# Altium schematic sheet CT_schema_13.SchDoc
size 387 x 385 mm
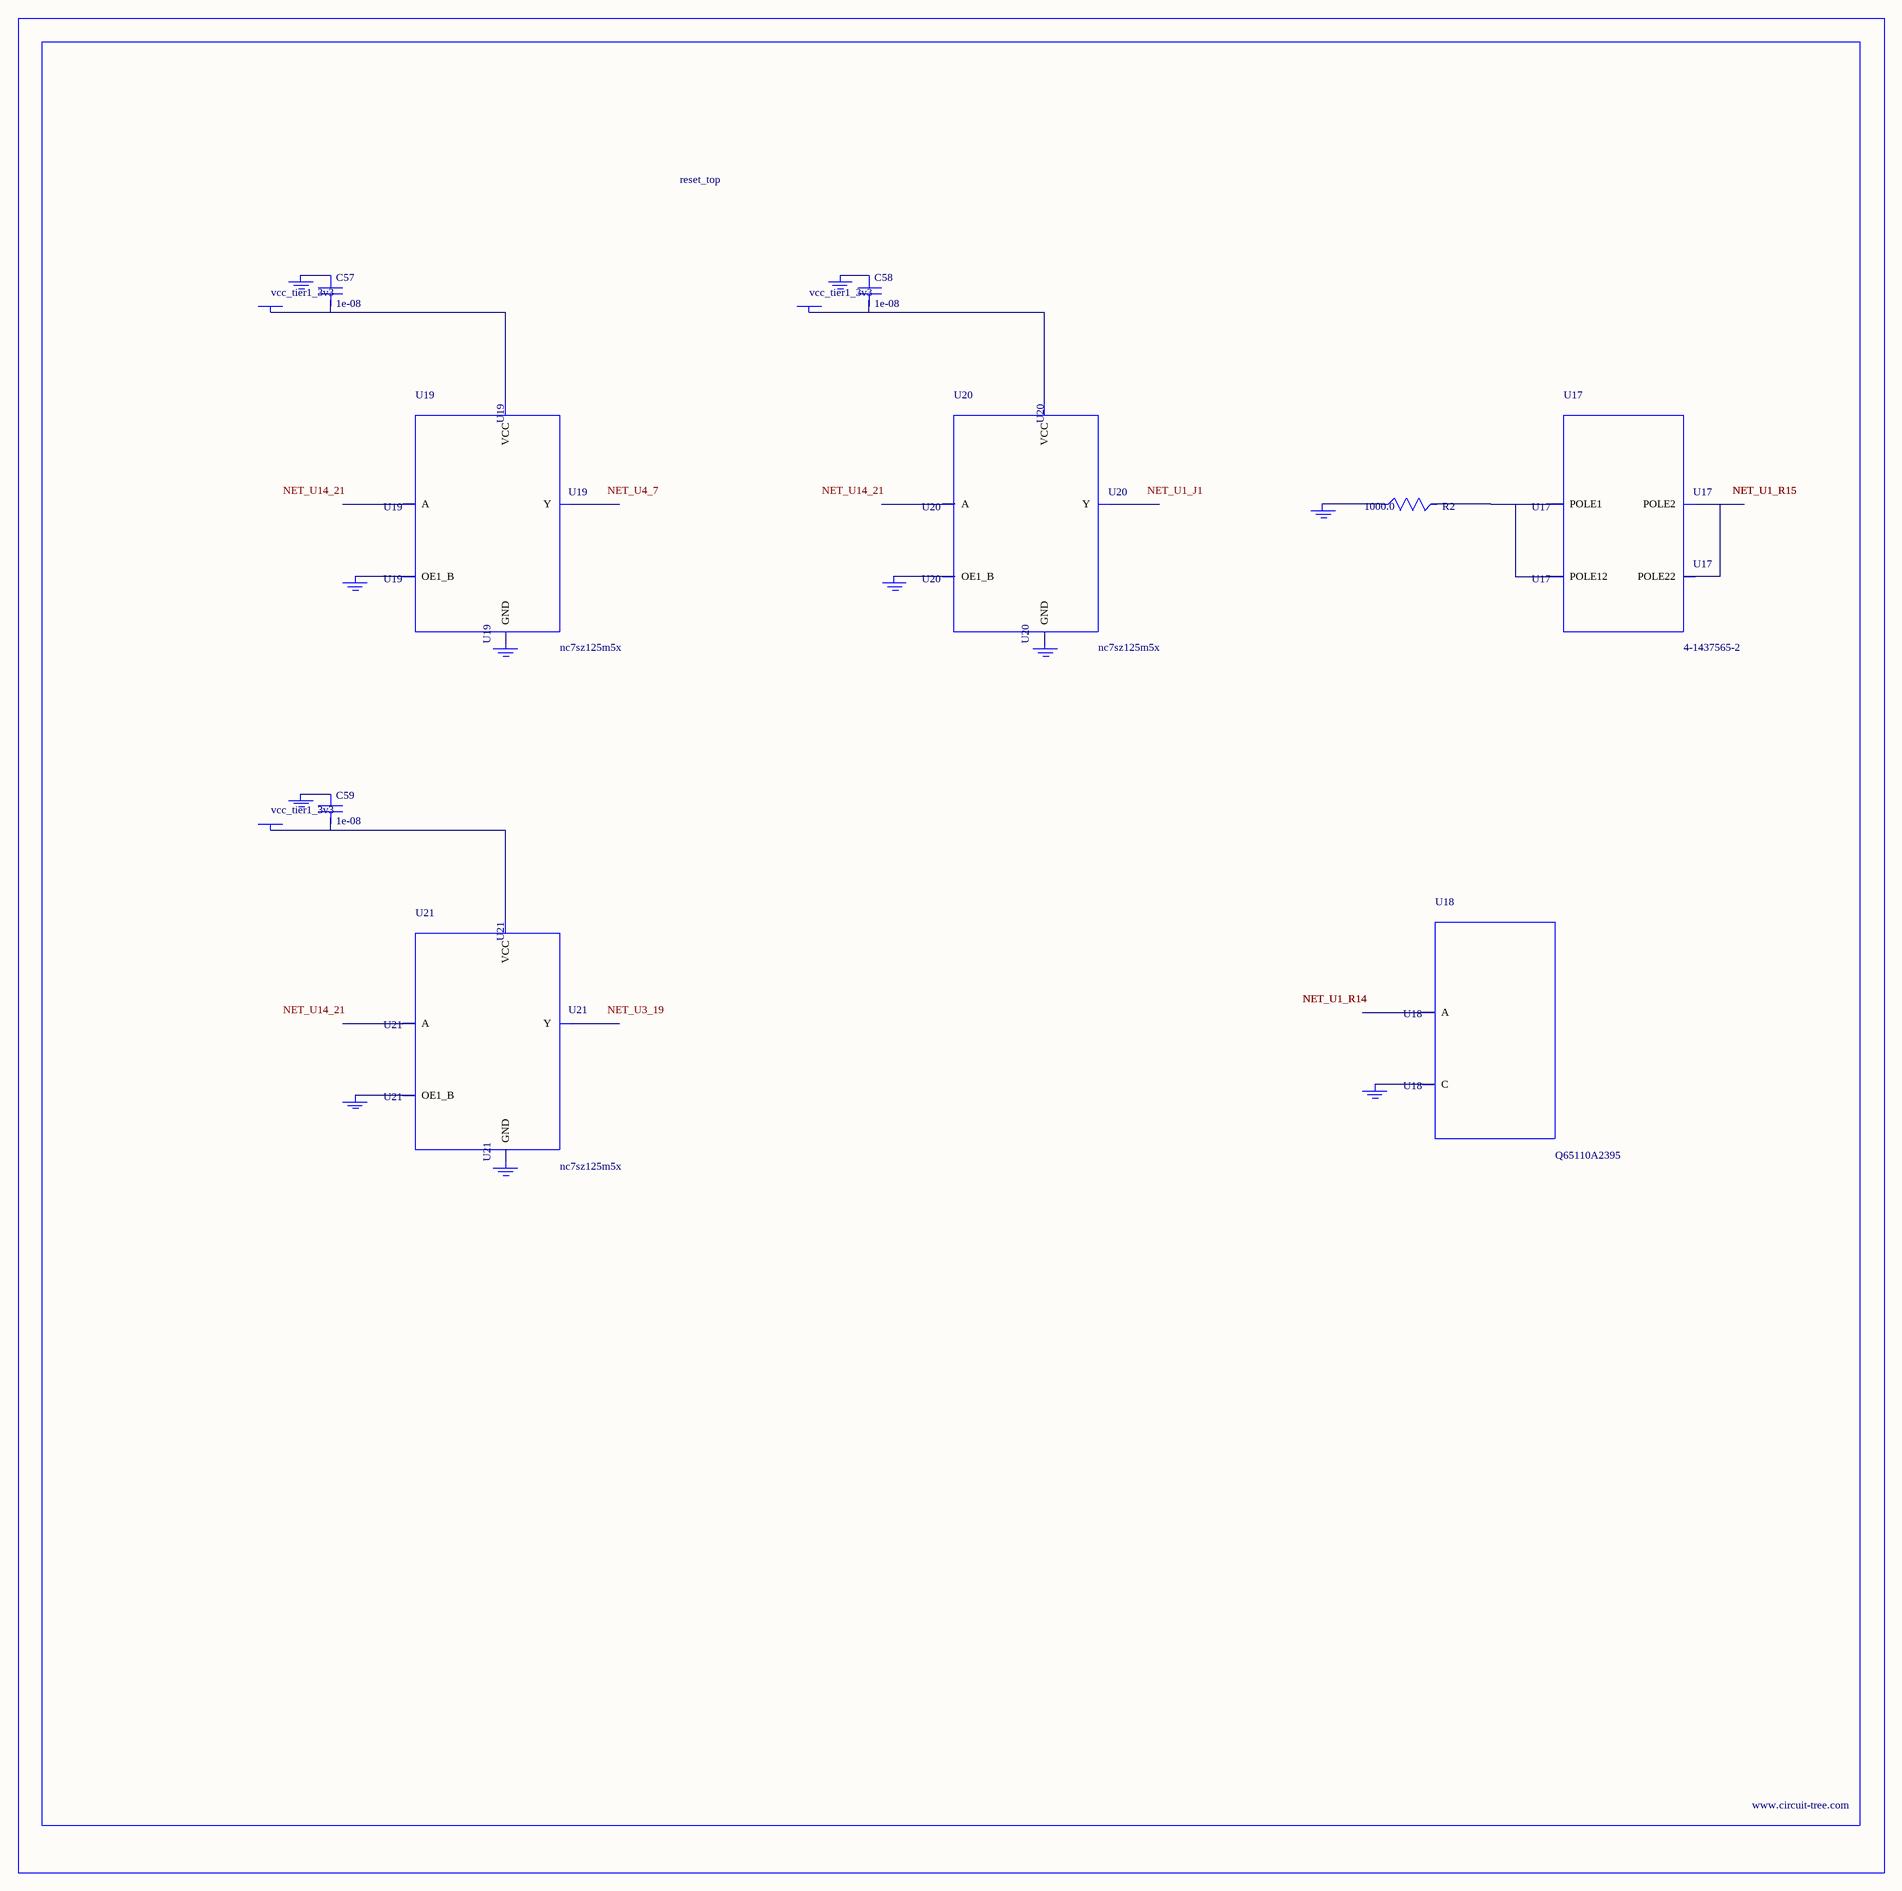
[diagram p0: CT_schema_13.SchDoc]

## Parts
BORDER12  (no value)
C57  1e-08  [C0402]
C58  1e-08  [C0402]
C59  1e-08  [C0402]
GND_INSTANCE_12_0  (no value)
GND_INSTANCE_12_1  (no value)
GND_INSTANCE_12_2  (no value)
GND_INSTANCE_12_3  (no value)
GND_INSTANCE_12_4  (no value)
GND_INSTANCE_12_5  (no value)
GND_INSTANCE_12_6  (no value)
GND_INSTANCE_12_7  (no value)
GND_INSTANCE_12_8  (no value)
GND_INSTANCE_12_9  (no value)
GND_INSTANCE_12_10  (no value)
POWER_INSTANCE_12_0  vcc_tier1_3v3
POWER_INSTANCE_12_1  vcc_tier1_3v3
POWER_INSTANCE_12_2  vcc_tier1_3v3
R2  1000.0  [R0603]
U17  4-1437565-2  [SW_4-1437565-2]
U18  Q65110A2395  [LGM67K-G1J2-24-Z]
U19  nc7sz125m5x  [NC7SZ125M5X]
U20  nc7sz125m5x  [NC7SZ125M5X]
U21  nc7sz125m5x  [NC7SZ125M5X]

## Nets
NetC57_1: C57.1 GND_INSTANCE_12_2.0(GND)
NetC57_2: C57.2 POWER_INSTANCE_12_0.0(PWR) U19.5(VCC)
NetC58_1: C58.1 GND_INSTANCE_12_5.0(GND)
NetC58_2: C58.2 POWER_INSTANCE_12_1.0(PWR) U20.5(VCC)
NetC59_1: C59.1 GND_INSTANCE_12_8.0(GND)
NetC59_2: C59.2 POWER_INSTANCE_12_2.0(PWR) U21.5(VCC)
NetGND_INSTANCE_12_0_0: GND_INSTANCE_12_0.0(GND) R2.1
NetGND_INSTANCE_12_1_0: GND_INSTANCE_12_1.0(GND) U18.C
NetGND_INSTANCE_12_3_0: GND_INSTANCE_12_3.0(GND) U19.1(OE1_B)
NetGND_INSTANCE_12_4_0: GND_INSTANCE_12_4.0(GND) U19.3(GND)
NetGND_INSTANCE_12_6_0: GND_INSTANCE_12_6.0(GND) U20.1(OE1_B)
NetGND_INSTANCE_12_7_0: GND_INSTANCE_12_7.0(GND) U20.3(GND)
NetGND_INSTANCE_12_9_0: GND_INSTANCE_12_9.0(GND) U21.1(OE1_B)
NetGND_INSTANCE_12_10_0: GND_INSTANCE_12_10.0(GND) U21.3(GND)
NetR2_2: R2.2 U17.1(POLE1) U17.2(POLE12)
NetU17_3: U17.3(POLE2) U17.4(POLE22)

Not connected (* = marked no-connect by the designer): U18 A; U19 2(A) 4(Y); U20 2(A) 4(Y); U21 2(A) 4(Y)

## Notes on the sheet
- Labels drawn without touching a wire or pin: NET_U1_J1, NET_U3_19, NET_U4_7, NET_U14_21

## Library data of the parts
BORDER12 = BORDER_PAGE12
C57-C59 = C0402C103K3RAC
GND_INSTANCE_12_0-GND_INSTANCE_12_10 = GND
POWER_INSTANCE_12_0-POWER_INSTANCE_12_2 = PWR
R2 = RC0603JR-071KL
